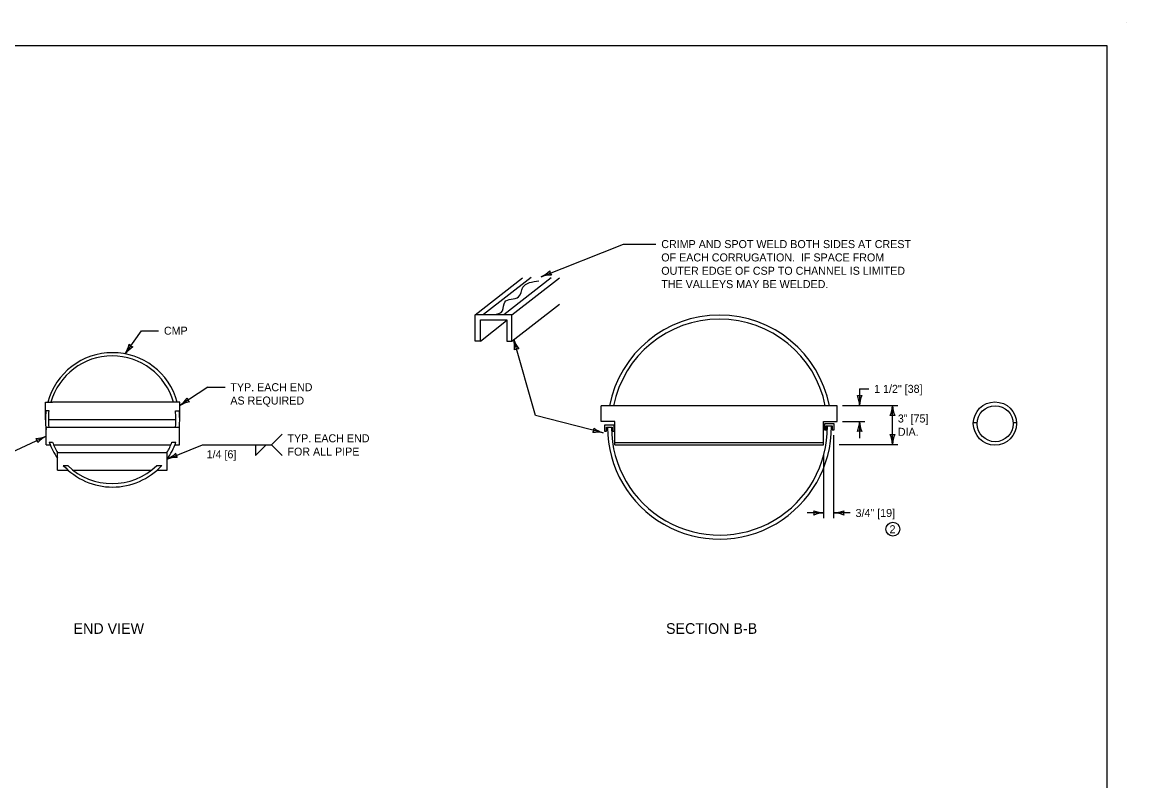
# Model space of a CAD drawing. Extents: x 49991.4 to 50021, y 49987.6 to 50011.4.
# Drawn here: x 50008.62 to 50016.9, y 49993.49 to 49999.18 of the extents above; entities that cross this region are included whole.
import ezdxf

# ---------------------------------------------------------------- set-up
doc = ezdxf.new("R2010")
doc.units = 0
for name, color, linetype in [('Level 1', 7, 'Continuous'), ('Level 2', 7, 'Continuous'), ('Level 3', 7, 'Continuous')]:
    doc.layers.add(name, color=color, linetype=linetype)

msp = doc.modelspace()

# ---------------------------------------------------------------- linework, layer by layer
at = {"layer": 'Level 1'}
for p, q in [((50016.9001, 49999.1756), (50016.9001, 49999.1756)), ((50012.0127, 49996.9823), (50012.3683, 49997.2588)), ((50012.0765, 49996.9869), (50012.4321, 49997.2635)), ((50012.2285, 49996.9846), (50012.584, 49997.2611)), ((50012.2893, 49996.9823), (50012.6448, 49997.2588)), ((50012.2893, 49996.7847), (50012.6448, 49997.0613)), ((50012.0127, 49996.7847), (50012.0127, 49996.9823)), ((50012.2893, 49996.9823), (50012.0127, 49996.9823)), ((50012.2893, 49996.7847), (50012.2893, 49996.9823)), ((50012.0522, 49996.7847), (50012.0522, 49996.9428)), ((50012.0522, 49996.9428), (50012.1674, 49996.9428)), ((50012.0522, 49996.7847), (50012.2488, 49996.9376)), ((50012.1674, 49996.9428), (50012.2465, 49996.9428)), ((50012.2465, 49996.9428), (50012.2498, 49996.9428)), ((50012.2498, 49996.9428), (50012.2498, 49996.7847)), ((50012.0522, 49996.7847), (50012.0127, 49996.7847)), ((50012.2498, 49996.7847), (50012.2893, 49996.7847)), ((50008.7906, 49996.1933), (50008.7906, 49996.3261)), ((50008.7906, 49996.3261), (50008.843, 49996.3261)), ((50009.7979, 49996.3261), (50008.843, 49996.3261)), ((50009.7979, 49996.1932), (50009.7979, 49996.3259)), ((50008.7947, 49996.2636), (50008.8169, 49996.2627)), ((50009.7652, 49996.2622), (50009.7933, 49996.2619)), ((50012.959, 49996.181), (50012.959, 49996.2995)), ((50014.7279, 49996.2995), (50012.959, 49996.2995)), ((50014.7279, 49996.181), (50014.7279, 49996.2995)), ((50009.77, 49996.1933), (50008.8131, 49996.1933)), ((50009.7979, 49996.1933), (50009.798, 49996.1933)), ((50013.0611, 49996.181), (50012.959, 49996.181)), ((50013.0561, 49996.1543), (50012.9821, 49996.1543)), ((50012.9821, 49996.1543), (50012.9821, 49996.1098)), ((50012.9833, 49996.1543), (50012.9833, 49996.1543)), ((50013.0561, 49996.1098), (50013.0561, 49996.1543)), ((50013.0612, 49996.0057), (50013.0611, 49996.181)), ((50014.6257, 49996.0057), (50014.6259, 49996.181)), ((50014.6259, 49996.181), (50014.7279, 49996.181)), ((50014.6315, 49996.1642), (50014.6315, 49996.1197)), ((50014.7056, 49996.1642), (50014.6327, 49996.1642)), ((50014.6327, 49996.1642), (50014.6327, 49996.1642)), ((50014.6463, 49996.1197), (50014.6463, 49996.1493)), ((50014.6463, 49996.1493), (50014.6907, 49996.1493)), ((50014.6907, 49996.1493), (50014.6907, 49996.1197)), ((50014.7056, 49996.1197), (50014.7056, 49996.1642)), ((50015.7497, 49996.1738), (50015.7785, 49996.1738)), ((50016.046, 49996.1738), (50016.0707, 49996.1738)), ((50008.7934, 49996.1401), (50009.795, 49996.1401)), ((50008.7957, 49996.0073), (50008.7957, 49996.1401)), ((50009.795, 49996.0073), (50009.795, 49996.1401)), ((50012.9821, 49996.1098), (50012.9969, 49996.1098)), ((50012.9969, 49996.1098), (50012.9969, 49996.1395)), ((50012.9969, 49996.1395), (50013.0413, 49996.1395)), ((50013.0413, 49996.1395), (50013.0413, 49996.1098)), ((50013.0413, 49996.1098), (50013.0561, 49996.1098)), ((50014.6315, 49996.1197), (50014.6463, 49996.1197)), ((50014.6907, 49996.1197), (50014.7056, 49996.1197)), ((50008.7957, 49996.0073), (50008.8269, 49996.0073)), ((50008.8195, 49996.0254), (50008.8439, 49996.0255)), ((50008.8509, 49996.0073), (50009.7319, 49996.0073)), ((50009.7396, 49996.0266), (50009.7692, 49996.026)), ((50009.7622, 49996.0073), (50009.795, 49996.0073)), ((50013.0612, 49996.0057), (50014.6257, 49996.0057)), ((50013.0616, 49996.0237), (50014.625, 49996.0237)), ((50008.8813, 49995.8174), (50008.8813, 49995.9502)), ((50008.8813, 49995.9502), (50009.7026, 49995.9502)), ((50009.7026, 49995.8171), (50009.7026, 49995.9499)), ((50008.8813, 49995.8174), (50008.9591, 49995.8174)), ((50008.9244, 49995.8517), (50008.9577, 49995.8517)), ((50008.9969, 49995.8174), (50009.5854, 49995.8172)), ((50009.6258, 49995.8522), (50009.6643, 49995.8519)), ((50009.6286, 49995.8171), (50009.7026, 49995.8171))]:
    msp.add_line(p, q, dxfattribs=at)
msp.add_lwpolyline([(49999.3835, 49998.9992), (50016.7501, 49998.9992), (50016.7501, 49987.7988), (49999.3835, 49987.7988)], close=True, dxfattribs=at)
for centre, radius in [((50015.9106, 49996.1662), 0.1621), ((50015.9118, 49996.1648), 0.1351), ((50015.9118, 49996.1648), 0.1351)]:
    msp.add_circle(centre, radius, dxfattribs=at)
for centre, radius, start, end in [((50013.8448, 49996.1394), 0.8395, 10.99048, 169.00952), ((50013.8448, 49996.1394), 0.8099, 11.39786, 168.60214), ((50009.2942, 49996.1937), 0.5037, 15.36638, 164.7505), ((50009.2915, 49996.1945), 0.4785, 16.0589, 164.04306), ((50009.2942, 49996.199), 0.5037, 172.62655, 180.72799), ((50009.3166, 49996.1999), 0.5037, 172.82723, 180.72799), ((50009.2915, 49996.1945), 0.4785, 353.56628, 8.13723), ((50009.2942, 49996.1937), 0.5037, 353.94975, 7.78819), ((50009.2942, 49996.1937), 0.5037, 180.12655, 188.22799), ((50009.2915, 49996.1945), 0.4785, 180.12655, 186.54761), ((50013.8448, 49996.1394), 0.8395, 180.14989, 0.44966), ((50013.8448, 49996.1394), 0.8099, 180.15537, 0.46612), ((50009.2942, 49996.1937), 0.5037, 199.51767, 214.91497), ((50009.2915, 49996.1945), 0.4785, 200.68658, 211.01724), ((50009.2915, 49996.1945), 0.4785, 329.16103, 339.45222), ((50009.2942, 49996.1937), 0.5037, 324.17238, 340.55174), ((50009.2942, 49996.1937), 0.5037, 222.75607, 317.27331), ((50009.2915, 49996.1945), 0.4785, 225.75589, 314.31688)]:
    msp.add_arc(centre, radius, start, end, dxfattribs=at)
msp.add_spline([(50012.15, 49996.9827), (50012.219, 49997.0122), (50012.2352, 49997.0771), (50012.3385, 49997.1154), (50012.371, 49997.1873), (50012.4916, 49997.2349)], degree=3, dxfattribs=at)
at = {"layer": 'Level 2'}
msp.add_circle((50015.1456, 49995.3738), 0.052, dxfattribs=at)
at = {"layer": 'Level 3'}
for p, q in [((50012.5079, 49997.267), (50013.1257, 49997.5114)), ((50013.1257, 49997.5114), (50013.3687, 49997.5114)), ((50009.389, 49996.6884), (50009.5111, 49996.8622)), ((50009.5111, 49996.8622), (50009.6396, 49996.8622)), ((50010.0091, 49996.4385), (50010.1376, 49996.4385)), ((50014.8956, 49996.4263), (50014.8956, 49996.3013)), ((50014.8956, 49996.4263), (50014.9648, 49996.4263)), ((50014.7679, 49996.3013), (50015.1825, 49996.3013)), ((50015.1425, 49996.0091), (50015.1425, 49996.3013)), ((50014.7679, 49996.182), (50014.9356, 49996.182)), ((50014.8956, 49996.182), (50014.8956, 49996.057)), ((50010.4858, 49996.0056), (50010.5658, 49996.0856)), ((50014.7022, 49995.4558), (50014.7022, 49996.0797)), ((50009.703, 49995.8994), (50009.9695, 49996.0056)), ((50009.9695, 49996.0056), (50010.4858, 49996.0056)), ((50010.3658, 49996.0056), (50010.3658, 49995.9256)), ((50010.3658, 49995.9256), (50010.4458, 49996.0056)), ((50010.4858, 49996.0056), (50010.5658, 49995.9256)), ((50014.7422, 49996.0091), (50015.1825, 49996.0091)), ((50014.6281, 49995.4558), (50014.6281, 49995.9257)), ((50014.6281, 49995.4958), (50014.503, 49995.4958)), ((50014.8256, 49995.4958), (50014.7022, 49995.4958))]:
    msp.add_line(p, q, dxfattribs=at)
for points in [[(50012.4666, 49996.2267), (50012.303, 49996.7953)], [(50010.0091, 49996.4385), (50009.7979, 49996.3008)], [(50012.9737, 49996.0956), (50012.4666, 49996.2267)], [(50008.5352, 49995.9489), (50008.7957, 49996.072)]]:
    msp.add_lwpolyline(points, dxfattribs=at)
for centre, radius, start, end in [((50012.4116, 49997.4792), 0.233, 294.41093, 313.66078), ((50012.6271, 49997.3142), 0.0548, 183.72244, 219.4448), ((50012.5811, 49997.0571), 0.2223, 89.03963, 109.22314), ((50009.1919, 49996.8127), 0.233, 327.73877, 346.98862), ((50009.5655, 49996.5532), 0.2223, 122.36747, 142.55098), ((50009.4627, 49996.7933), 0.0548, 217.05027, 252.77264), ((50012.087, 49996.7427), 0.2223, 353.5105, 13.69401), ((50012.5234, 49996.8707), 0.233, 198.8818, 218.13165), ((50012.3384, 49996.6721), 0.0548, 88.19331, 123.91567), ((50009.6612, 49996.4894), 0.233, 305.93784, 325.18769), ((50009.9116, 49996.1097), 0.2223, 100.56654, 120.75004), ((50009.9053, 49996.3708), 0.0548, 195.24934, 230.97171), ((50014.8956, 49996.4295), 0.0548, 252.13882, 287.86118), ((50014.6629, 49996.2898), 0.233, 2.82731, 22.07716), ((50015.1177, 49996.2921), 0.2223, 157.45601, 177.63952), ((50014.9204, 49996.3105), 0.2223, 337.45601, 357.63952), ((50015.1425, 49996.1731), 0.0548, 72.13882, 107.86118), ((50015.3752, 49996.3128), 0.233, 182.82731, 202.07716), ((50014.6735, 49996.1912), 0.2223, 337.45601, 357.63952), ((50015.1283, 49996.1935), 0.233, 182.82731, 202.07716), ((50008.7091, 49996.2768), 0.2223, 272.74922, 292.93273), ((50008.9055, 49995.8665), 0.233, 118.12052, 137.37037), ((50012.8496, 49996.1277), 0.0548, 327.64358, 3.36594), ((50012.9266, 49995.8674), 0.233, 78.33208, 97.58192), ((50013.0382, 49996.3084), 0.2223, 232.96078, 253.14428), ((50014.8956, 49996.0538), 0.0548, 72.13882, 107.86118), ((50015.1425, 49996.1373), 0.0548, 252.13882, 287.86118), ((50014.9098, 49995.9976), 0.233, 2.82731, 22.07716), ((50015.3646, 49995.9999), 0.2223, 157.45601, 177.63952), ((50008.6798, 49996.0172), 0.0548, 7.43203, 43.15439), ((50009.6062, 49996.1113), 0.233, 294.55455, 313.8044), ((50009.7767, 49995.6897), 0.2223, 89.18325, 109.36676), ((50009.8221, 49995.9469), 0.0548, 183.86606, 219.58842), ((50014.6373, 49995.7179), 0.2223, 247.45601, 267.63952), ((50014.4999, 49995.4958), 0.0548, 342.13882, 17.86118), ((50014.6396, 49995.2631), 0.233, 92.82731, 112.07716), ((50014.6907, 49995.7285), 0.233, 272.82731, 292.07716), ((50014.693, 49995.2737), 0.2223, 67.45601, 87.63952), ((50014.8304, 49995.4958), 0.0548, 162.13882, 197.86118)]:
    msp.add_arc(centre, radius, start, end, dxfattribs=at)

# ---------------------------------------------------------------- texts
at = {"layer": 'Level 2'}
for s, height, p in [('CRIMP AND SPOT WELD BOTH SIDES AT CREST', 0.06, (50013.4087, 49997.4814)), ('OF EACH CORRUGATION.  IF SPACE FROM', 0.06, (50013.4087, 49997.3814)), ('OUTER EDGE OF CSP TO CHANNEL IS LIMITED', 0.06, (50013.4087, 49997.2814)), ('THE VALLEYS MAY BE WELDED.', 0.06, (50013.4087, 49997.1814)), ('CMP', 0.06, (50009.6796, 49996.8322)), ('TYP. EACH END', 0.06, (50010.1776, 49996.4085)), ('1 1/2" [38]', 0.06, (50015.0048, 49996.3963)), ('AS REQUIRED', 0.06, (50010.1776, 49996.3085)), ('3" [75]', 0.06, (50015.1825, 49996.174)), ('TYP. EACH END', 0.06, (50010.6058, 49996.0256)), ('DIA.', 0.06, (50015.1825, 49996.074)), ('FOR ALL PIPE', 0.06, (50010.6058, 49995.9256)), ('1/4 [6]', 0.06, (50009.9997, 49995.9056)), ('3/4" [19]', 0.06, (50014.8656, 49995.4658)), ('2', 0.06, (50015.1204, 49995.3438)), ('END VIEW', 0.08, (50009.0015, 49994.5896)), ('SECTION B-B', 0.08, (50013.4443, 49994.5896))]:
    msp.add_text(s, height=height, dxfattribs=at).set_placement(p)

doc.saveas('drawing.dxf')
